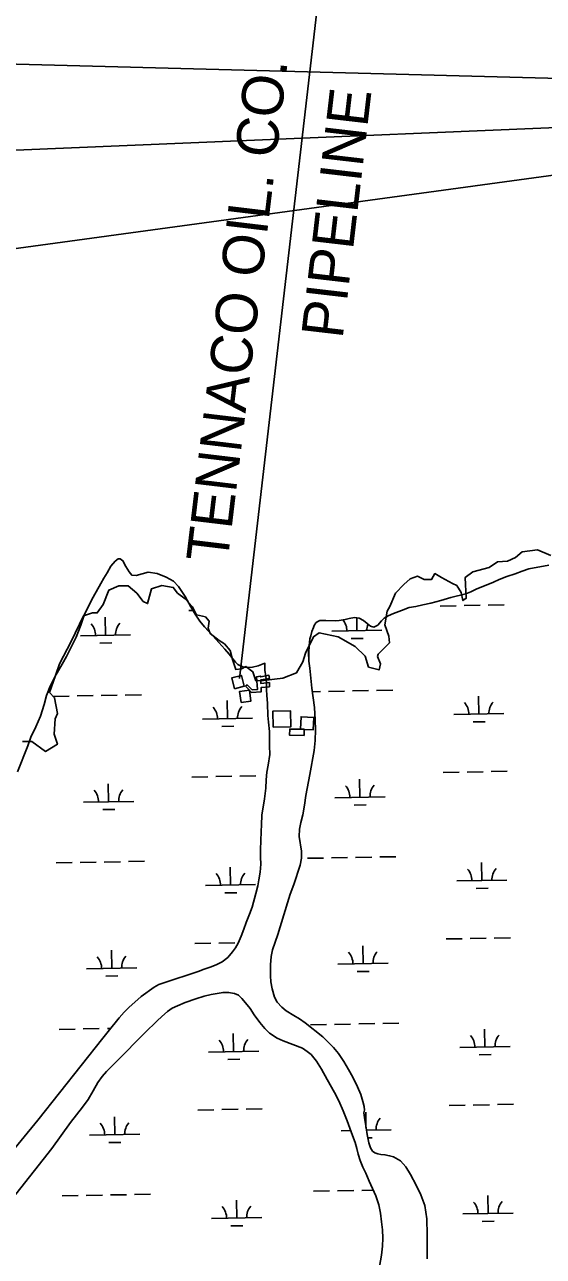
# Model space of a CAD drawing. Extents: x 3957609 to 3995875, y 234277 to 260273.
# Drawn here: x 3969134 to 3970170, y 243942 to 246402 of the extents above; entities that cross this region are included whole.
import ezdxf

# ---------------------------------------------------------------- set-up
doc = ezdxf.new("R2010")
doc.units = 0
for name, color, linetype in [('V-BLDG-OTLN', 7, 'Continuous'), ('V-CHAN-DOCK', 7, 'Continuous'), ('V-RIVR-EDGE', 7, 'Continuous'), ('V-TOPO-MINR', 7, 'Continuous'), ('V-TOPO-SHOR', 7, 'Continuous'), ('V-UTIL-IDEN', 7, 'Continuous'), ('V-UTIL-LINE', 7, 'Continuous'), ('V-WETL-SWMP', 7, 'Continuous')]:
    doc.layers.add(name, color=color, linetype=linetype)

msp = doc.modelspace()

# ---------------------------------------------------------------- linework, layer by layer
at = {"layer": 'V-BLDG-OTLN'}
for points in [[(3969553.369, 245075.43), (3969547.733, 245097.137), (3969567.135, 245102.175), (3969572.771, 245080.468)], [(3969566.263, 245048.294), (3969563.363, 245070.159), (3969583.239, 245072.792), (3969586.137, 245050.93)], [(3969630.261, 244998.835), (3969629.929, 245030.857), (3969665.173, 245031.222), (3969665.507, 244999.199)], [(3969692.289, 244994.366), (3969692.291, 244994.85), (3969685.18, 244994.893), (3969686.347, 245019.466), (3969711.681, 245018.264), (3969710.506, 244993.502)], [(3969685.18, 244994.893), (3969685.172, 244994.704), (3969692.289, 244994.366), (3969692.215, 244982.361), (3969663.342, 244982.535), (3969663.418, 244995.022)], [(3969692.289, 244994.366), (3969685.172, 244994.704), (3969685.18, 244994.893), (3969692.291, 244994.85)]]:
    msp.add_lwpolyline(points, close=True, dxfattribs=at)
at = {"layer": 'V-CHAN-DOCK'}
msp.add_lwpolyline([(3969575.219, 245080.575), (3969587.021, 245068.369), (3969606.639, 245069.602), (3969606.633, 245078.31), (3969622.841, 245079.7), (3969623.038, 245087.98), (3969606.011, 245085.951), (3969606.051, 245093.467), (3969622.907, 245095.859), (3969622.03, 245102.603), (3969605.519, 245099.056), (3969605.064, 245100.971), (3969597.468, 245099.453), (3969599.5, 245074.218), (3969588.619, 245073.157), (3969578.563, 245083.231), (3969575.219, 245080.575)], dxfattribs=at)
at = {"layer": 'V-RIVR-EDGE'}
for points in [[(3969695.061, 245146.435), (3969711.158, 245179.575), (3969722.52, 245187.15), (3969760.395, 245179.575), (3969794.482, 245159.691), (3969814.366, 245140.754), (3969820.994, 245118.976), (3969841.825, 245113.295), (3969844.666, 245125.604), (3969838.985, 245139.807), (3969839.931, 245144.541), (3969851.294, 245155.904), (3969862.656, 245167.266), (3969861.709, 245180.522), (3969853.187, 245203.247), (3969857.922, 245230.706), (3969863.603, 245240.175), (3969874.965, 245266.687), (3969891.062, 245283.73), (3969904.318, 245295.093), (3969918.521, 245300.774), (3969931.777, 245294.146), (3969946.927, 245294.146), (3969953.555, 245305.508), (3969966.811, 245297.933), (3969988.589, 245285.624), (3969997.111, 245281.837), (3970005.633, 245267.634), (3970009.42, 245251.537), (3970016.048, 245256.271), (3970014.155, 245297.933), (3970029.304, 245309.296), (3970061.498, 245317.817), (3970078.541, 245329.18), (3970098.426, 245330.127), (3970114.522, 245337.702), (3970127.778, 245349.064), (3970158.078, 245352.851), (3970184.59, 245341.489)], [(3969129.783, 244970.318), (3969148.72, 244970.318), (3969176.179, 244950.434), (3969199.851, 244964.637), (3969193.223, 244984.521), (3969195.116, 245015.768), (3969199.851, 245026.183), (3969194.169, 245057.43), (3969183.754, 245067.845), (3969196.063, 245101.932), (3969203.638, 245125.604), (3969227.31, 245170.107), (3969251.928, 245221.237), (3969269.919, 245226.918), (3969279.387, 245226.918), (3969290.75, 245243.962), (3969302.112, 245272.368), (3969321.996, 245280.89), (3969340.933, 245280.89), (3969357.977, 245266.687), (3969371.233, 245249.643), (3969379.755, 245245.856), (3969387.33, 245275.209), (3969408.161, 245281.837), (3969430.886, 245278.049), (3969439.407, 245266.687), (3969454.557, 245255.324), (3969469.707, 245239.228), (3969477.282, 245223.131), (3969495.272, 245219.343), (3969502.847, 245210.822), (3969500.954, 245196.619), (3969504.741, 245186.203), (3969522.732, 245172), (3969533.147, 245165.372), (3969544.509, 245152.116), (3969549.244, 245134.126), (3969555.872, 245114.241), (3969567.234, 245115.188), (3969575.756, 245119.923), (3969589.959, 245109.507), (3969595.64, 245091.517)], [(3969595.69, 245091.497), (3969611.081, 245091.94), (3969649.615, 245096.812), (3969677.076, 245107.442), (3969689.921, 245129.146), (3969695.015, 245146.641)]]:
    msp.add_lwpolyline(points, dxfattribs=at)
at = {"layer": 'V-TOPO-MINR'}
for points in [[(3968018.214, 246314.387), (3968169.95, 246323.752), (3968183.086, 246324.466), (3968196.227, 246325.051), (3968209.375, 246325.442), (3968222.528, 246325.705), (3968477.968, 246328.931), (3968618.838, 246329.888), (3968759.702, 246329.746), (3968900.553, 246327.959), (3969041.398, 246325.074), (3970886.166, 246276.501), (3970886.6, 246276.508), (3970887.46, 246276.621), (3970887.884, 246276.714), (3971224.276, 246358.726)], [(3967984.26, 246085.689), (3968092.213, 246090.995), (3968141.873, 246093.558), (3968191.524, 246096.284), (3968241.162, 246099.254), (3968290.79, 246102.387), (3968851.891, 246139.195), (3968877.6, 246141.493), (3970879.56, 246225.354), (3970881.146, 246225.397), (3970884.286, 246225.855), (3970885.836, 246226.204), (3971195.807, 246303.452)], [(3967993.694, 245839.928), (3968037.136, 245840.981), (3968087.474, 245842.556), (3968178.984, 245845.901), (3968183.56, 245846.084), (3968188.135, 245846.289), (3968192.709, 245846.525), (3968197.281, 245846.782), (3968292.438, 245852.461), (3968344.567, 245855.838), (3968396.67, 245859.567), (3968448.732, 245863.824), (3970882.382, 246196.277), (3970883.256, 246197.118), (3970883.849, 246197.376), (3970910.475, 246204.139), (3970924.528, 246207.257), (3970938.667, 246209.799), (3970952.935, 246211.476), (3970967.288, 246212.578), (3971208.52, 246223.719)]]:
    msp.add_lwpolyline(points, dxfattribs=at)
at = {"layer": 'V-TOPO-SHOR'}
msp.add_line((3969613.588, 245117.869), (3969613.92, 245126.46), dxfattribs=at)
for points in [[(3969703.704, 245174.973), (3969702.312, 245161.073), (3969701.353, 245148.409), (3969701.406, 245130.781), (3969703.366, 245116.683), (3969707.733, 245076.571), (3969712.894, 245037.995), (3969714.088, 245013.699), (3969714.722, 244993.59), (3969714.26, 244972.414), (3969712.57, 244951.872), (3969703.53, 244904.379), (3969695.807, 244862.278), (3969692.899, 244843.148), (3969689.682, 244823.866), (3969685.749, 244808.617), (3969682.925, 244795.204), (3969682.247, 244780.371), (3969687.238, 244751.383), (3969687.185, 244737.16), (3969684.658, 244722.816), (3969672.042, 244684.651), (3969664.491, 244665.124), (3969658.833, 244648.043), (3969639.975, 244584.611), (3969629.165, 244553.69), (3969626.499, 244540.429), (3969625.331, 244523.902), (3969625.172, 244502.256), (3969626.077, 244490.028), (3969628.807, 244475.763), (3969633.05, 244459.156), (3969638.324, 244449.647), (3969647.919, 244439.612), (3969656.311, 244431.914), (3969671.643, 244422.878), (3969683.292, 244415.751), (3969694.163, 244408.325), (3969729.931, 244379.819), (3969741.824, 244368.358), (3969751.267, 244358.481), (3969760.839, 244346.899), (3969771.434, 244330.974), (3969780.936, 244314.6), (3969789.223, 244299.635), (3969798.989, 244280.011), (3969805.269, 244265.229), (3969809.703, 244251.096), (3969812.185, 244241.007), (3969812.537, 244233.272), (3969811.691, 244228.336), (3969812.795, 244219.198), (3969814.364, 244210.052), (3969815.894, 244198.278), (3969818.171, 244184.794), (3969821.182, 244168.512), (3969824.589, 244158.26), (3969828.669, 244151.704), (3969833.414, 244148.389), (3969839.257, 244146.14), (3969845.739, 244145.272), (3969853.614, 244144.54), (3969863.016, 244142.392), (3969870.715, 244140.117), (3969884.52, 244132.494), (3969895.17, 244120.589), (3969904.529, 244104.989), (3969915.973, 244083.795), (3969925.585, 244064.173), (3969933.627, 244043.025), (3969937.569, 244016.372), (3969938.04, 243984.823), (3969937.639, 243957.306), (3969937.957, 243936.582)], [(3969066.328, 244098.768), (3969160.923, 244213.361), (3969290.098, 244377.552), (3969300.957, 244390.538), (3969323.006, 244418.204), (3969332.91, 244429.348), (3969342.165, 244438.492), (3969367.228, 244460.856), (3969392.705, 244479.661), (3969402.208, 244484.469), (3969411.844, 244487.886), (3969480.521, 244510.856), (3969492.807, 244515.626), (3969504.616, 244519.63), (3969516.742, 244524.09), (3969528.735, 244530.103), (3969539.993, 244538.752), (3969549.432, 244549.903), (3969555.423, 244557.702), (3969560.821, 244567.52), (3969566.9, 244581.346), (3969572.053, 244595.498), (3969576.417, 244608.576), (3969583.302, 244624.868), (3969588.457, 244639.173), (3969596.127, 244666.739), (3969599.75, 244681.995), (3969602.087, 244693.867), (3969604.47, 244708.986), (3969605.632, 244725.048), (3969605.064, 244739.284), (3969605.134, 244754.59), (3969605.539, 244771.902), (3969606.271, 244790.291), (3969607.393, 244803.728), (3969607.829, 244823.205), (3969612.935, 244855.293), (3969616.033, 244877.049), (3969616.279, 244893.899), (3969617.582, 244909.034), (3969620.566, 244922.905), (3969624.127, 244944.501), (3969623.445, 244961.52), (3969623.476, 244974.2), (3969623.24, 244989.975), (3969620.887, 245008.872), (3969619.529, 245021.881), (3969618.954, 245046.166), (3969617.651, 245062.884), (3969617.18, 245073.095), (3969617.221, 245086.549), (3969615.581, 245101.262), (3969613.574, 245112.114), (3969613.588, 245117.869)], [(3969843.058, 243921.263), (3969847.097, 243943.781), (3969848.752, 243962.002), (3969849.45, 243978.073), (3969849.071, 243994.625), (3969846.829, 244010.583), (3969844.611, 244028.087), (3969841.287, 244044.217), (3969835.21, 244062.242), (3969822.337, 244091.497), (3969815.464, 244107.988), (3969809.762, 244119.977), (3969804.386, 244133.043), (3969799.932, 244145.788), (3969797.312, 244157.113), (3969793.929, 244168.914), (3969789.028, 244182.901), (3969783.521, 244197.516), (3969778.477, 244212.278), (3969770.416, 244232.187), (3969761.274, 244252.112), (3969753.016, 244269.085), (3969738.084, 244294.97), (3969726.787, 244315.7), (3969717.125, 244331.766), (3969706.338, 244344.911), (3969698.541, 244351.055), (3969689.045, 244357.223), (3969650.143, 244372.323), (3969638.31, 244377.287), (3969623.455, 244387.245), (3969613.85, 244396.661), (3969603.977, 244408.866), (3969592.758, 244424.182), (3969584.433, 244436.518), (3969575.481, 244448.244), (3969567.877, 244457.014), (3969561.161, 244463.144), (3969553.021, 244466.818), (3969541.607, 244468.837), (3969530.628, 244468.69), (3969506.443, 244464.401), (3969492.793, 244461.352), (3969476.018, 244456.185), (3969454.876, 244448.451), (3969439.17, 244442.338), (3969428.586, 244437.546), (3969419.208, 244430.724), (3969408.393, 244420.521), (3969398.837, 244412.001), (3969374.523, 244388.232), (3969318.033, 244331.377), (3969297.483, 244311.11), (3969288.833, 244301.03), (3969280.456, 244288.627), (3969271.097, 244272.219), (3969260.8, 244255.204), (3969250.056, 244239.434), (3969225.957, 244209.169), (3969188.554, 244156.986), (3969109.631, 244056.698)]]:
    msp.add_lwpolyline(points, dxfattribs=at)
at = {"layer": 'V-UTIL-LINE'}
msp.add_line((3969563.256, 245095.865), (3969783.41, 246998.629), dxfattribs=at)
at = {"layer": 'V-WETL-SWMP'}
for p, q in [((3969462.13, 245231.736), (3969470.115, 245231.882)), ((3969963.955, 245240.861), (3969995.949, 245241.443)), ((3970011.947, 245241.734), (3970043.941, 245242.316)), ((3970059.939, 245242.607), (3970091.934, 245243.188)), ((3969295.937, 245182.277), (3969295.283, 245218.271)), ((3969797.762, 245191.402), (3969797.293, 245217.222)), ((3969245.946, 245181.368), (3969345.929, 245183.186)), ((3969747.771, 245190.493), (3969847.754, 245192.311)), ((3969284.22, 245166.63), (3969308.216, 245167.067)), ((3969786.045, 245175.755), (3969810.041, 245176.191)), ((3969191.294, 245060.283), (3969223.289, 245060.865)), ((3969239.286, 245061.156), (3969271.281, 245061.738)), ((3969287.278, 245062.029), (3969319.273, 245062.61)), ((3969335.27, 245062.901), (3969367.265, 245063.483)), ((3969708.653, 245069.691), (3969725.114, 245069.99)), ((3969741.111, 245070.281), (3969773.106, 245070.862)), ((3969789.103, 245071.153), (3969821.098, 245071.735)), ((3969837.095, 245072.026), (3969869.09, 245072.608)), ((3970041.3, 245024.989), (3970040.646, 245060.983)), ((3969539.475, 245015.864), (3969538.821, 245051.858)), ((3969489.483, 245014.955), (3969589.467, 245016.773)), ((3969991.308, 245024.08), (3970091.292, 245025.898)), ((3970029.583, 245009.342), (3970053.579, 245009.778)), ((3969527.758, 245000.217), (3969551.754, 245000.654)), ((3969970.003, 244908.241), (3970001.997, 244908.823)), ((3970017.995, 244909.114), (3970049.99, 244909.696)), ((3970065.987, 244909.986), (3970097.982, 244910.568)), ((3969301.985, 244849.657), (3969301.331, 244885.651)), ((3969468.178, 244899.116), (3969500.172, 244899.698)), ((3969516.17, 244899.989), (3969548.164, 244900.571)), ((3969564.162, 244900.862), (3969596.157, 244901.444)), ((3969803.81, 244858.782), (3969803.156, 244894.776)), ((3969753.819, 244857.873), (3969853.802, 244859.691)), ((3969251.994, 244848.748), (3969351.977, 244850.566)), ((3969290.268, 244834.01), (3969314.264, 244834.447)), ((3969792.093, 244843.135), (3969816.089, 244843.571)), ((3969699.167, 244736.788), (3969731.162, 244737.37)), ((3969747.159, 244737.661), (3969779.154, 244738.242)), ((3969795.151, 244738.533), (3969827.146, 244739.115)), ((3969843.143, 244739.406), (3969875.138, 244739.988)), ((3969197.342, 244727.663), (3969229.337, 244728.245)), ((3969245.334, 244728.536), (3969277.329, 244729.118)), ((3969293.326, 244729.409), (3969325.321, 244729.99)), ((3969341.318, 244730.281), (3969373.313, 244730.863)), ((3969545.523, 244683.244), (3969544.869, 244719.238)), ((3970047.348, 244692.369), (3970046.694, 244728.363)), ((3969997.356, 244691.46), (3970097.34, 244693.278)), ((3969495.531, 244682.335), (3969595.515, 244684.153)), ((3969533.806, 244667.597), (3969557.802, 244668.034)), ((3970035.631, 244676.722), (3970059.627, 244677.158)), ((3969474.226, 244566.496), (3969506.22, 244567.078)), ((3969522.218, 244567.369), (3969554.213, 244567.951)), ((3969976.051, 244575.621), (3970008.045, 244576.203)), ((3970024.043, 244576.494), (3970056.038, 244577.076)), ((3970072.035, 244577.366), (3970104.03, 244577.948)), ((3969308.033, 244517.037), (3969307.379, 244553.031)), ((3969809.858, 244526.162), (3969809.204, 244562.156)), ((3969258.042, 244516.128), (3969358.025, 244517.946)), ((3969759.867, 244525.253), (3969859.85, 244527.071)), ((3969296.316, 244501.39), (3969320.312, 244501.827)), ((3969798.141, 244510.515), (3969822.137, 244510.951)), ((3969203.39, 244395.043), (3969235.385, 244395.625)), ((3969251.382, 244395.916), (3969283.377, 244396.498)), ((3969299.374, 244396.789), (3969306.035, 244396.91)), ((3969705.215, 244404.168), (3969737.21, 244404.75)), ((3969753.207, 244405.041), (3969785.202, 244405.622)), ((3969801.199, 244405.913), (3969833.194, 244406.495)), ((3969849.191, 244406.786), (3969881.186, 244407.368)), ((3970053.396, 244359.749), (3970052.742, 244395.743)), ((3969551.571, 244350.624), (3969550.917, 244386.618)), ((3969501.579, 244349.715), (3969601.563, 244351.533)), ((3970003.404, 244358.84), (3970103.388, 244360.658)), ((3970041.679, 244344.102), (3970065.675, 244344.538)), ((3969539.854, 244334.977), (3969563.85, 244335.414)), ((3969982.099, 244243.001), (3970014.094, 244243.583)), ((3970030.091, 244243.874), (3970062.086, 244244.456)), ((3970078.083, 244244.746), (3970110.078, 244245.328)), ((3969314.082, 244184.417), (3969313.427, 244220.411)), ((3969480.274, 244233.876), (3969512.269, 244234.458)), ((3969528.266, 244234.749), (3969560.261, 244235.331)), ((3969576.258, 244235.622), (3969608.253, 244236.203)), ((3969815.809, 244198.927), (3969815.252, 244229.536)), ((3969816.691, 244193.556), (3969865.898, 244194.451)), ((3969264.09, 244183.508), (3969364.073, 244185.326)), ((3969302.364, 244168.77), (3969326.36, 244169.207)), ((3969765.915, 244192.633), (3969785.228, 244192.984)), ((3969819.396, 244178.171), (3969828.185, 244178.331)), ((3969711.263, 244071.548), (3969743.258, 244072.13)), ((3969759.255, 244072.421), (3969791.25, 244073.002)), ((3969807.247, 244073.293), (3969830.164, 244073.71)), ((3969209.438, 244062.423), (3969241.433, 244063.005)), ((3969257.43, 244063.296), (3969289.425, 244063.878)), ((3969305.422, 244064.169), (3969337.417, 244064.75)), ((3969353.414, 244065.041), (3969385.409, 244065.623)), ((3969557.619, 244018.004), (3969556.965, 244053.998)), ((3970059.444, 244027.129), (3970058.79, 244063.123)), ((3970009.452, 244026.22), (3970109.436, 244028.038)), ((3969507.627, 244017.095), (3969607.611, 244018.913)), ((3969545.902, 244002.357), (3969569.898, 244002.794)), ((3970047.727, 244011.482), (3970071.723, 244011.918))]:
    msp.add_line(p, q, dxfattribs=at)
for points in [[(3969119.74, 244909.386), (3969140.36, 244961.386), (3969146.353, 244978.681), (3969156.738, 244999.17), (3969165.747, 245021.077), (3969172.912, 245044.251), (3969177.668, 245061.874), (3969185.24, 245081.008), (3969194.82, 245099.492), (3969209.309, 245124.733), (3969217.603, 245140.132), (3969237.253, 245178.799), (3969246.291, 245202.723), (3969253.094, 245222.333), (3969261.584, 245240.523), (3969270.851, 245258.856), (3969286.611, 245286.096), (3969292.347, 245296.411), (3969298.867, 245307.179), (3969306.508, 245320.415), (3969315.033, 245330.378), (3969321.003, 245335.413), (3969324.88, 245335.202), (3969330.41, 245331.242), (3969336.607, 245319.823), (3969342.813, 245309.024), (3969347.996, 245302.586), (3969356.984, 245301.68), (3969381.137, 245308.468), (3969398.793, 245306.038), (3969416.533, 245298.642), (3969431.619, 245290.198), (3969441.56, 245280.121), (3969454.764, 245259.599), (3969465.953, 245239.262), (3969474.425, 245224.24), (3969484.16, 245210.597), (3969493.149, 245199.138), (3969510.268, 245181.042), (3969533.935, 245154.316), (3969542.488, 245144.88), (3969549.798, 245135.307), (3969554.981, 245128.869), (3969560.027, 245123.674), (3969569.582, 245119.035), (3969579.341, 245117.807), (3969589.445, 245118.902)], [(3969671.643, 244422.878), (3969656.312, 244431.914), (3969647.919, 244439.613), (3969638.324, 244449.648), (3969633.05, 244459.157), (3969628.807, 244475.763), (3969626.076, 244490.028), (3969625.172, 244502.257), (3969625.331, 244523.902), (3969626.499, 244540.43), (3969629.166, 244553.689), (3969639.975, 244584.611), (3969658.832, 244648.043), (3969664.492, 244665.124), (3969672.043, 244684.652), (3969684.658, 244722.815), (3969687.186, 244737.159), (3969687.238, 244751.383), (3969682.247, 244780.371), (3969682.926, 244795.205), (3969685.75, 244808.616), (3969689.682, 244823.867), (3969692.9, 244843.148), (3969695.807, 244862.279), (3969703.531, 244904.38), (3969712.57, 244951.873), (3969714.26, 244972.413), (3969714.723, 244993.59), (3969714.087, 245013.7), (3969712.893, 245037.994), (3969707.733, 245076.57), (3969703.367, 245116.682), (3969701.407, 245130.781), (3969701.354, 245148.409), (3969702.311, 245161.074), (3969703.704, 245174.974), (3969705.969, 245181.303), (3969707.797, 245189.657), (3969710.714, 245198.15), (3969712.634, 245202.158), (3969715.967, 245207.231), (3969718.634, 245209.209), (3969723.95, 245211.926), (3969728.765, 245212.166), (3969735.439, 245212.224), (3969754.361, 245211.484), (3969762.439, 245211.987), (3969773.952, 245213.993), (3969782.357, 245215.733), (3969792.627, 245217.601), (3969801.928, 245216.845), (3969810.547, 245211.909), (3969818.215, 245205.59), (3969824.506, 245200.688), (3969831.77, 245198.565), (3969839.429, 245202.334), (3969846.85, 245211.072), (3969852.202, 245216.271), (3969860.189, 245221.276), (3969870.497, 245225.782), (3969886.418, 245232.069), (3969901.707, 245237.589), (3969915.091, 245240.188), (3969929.571, 245243.392), (3969945.289, 245246.422), (3969965.541, 245251.715), (3969985.033, 245258.105), (3970015.089, 245265.273), (3970025.39, 245269.314), (3970035.867, 245274.749), (3970070.677, 245288.676), (3970081.929, 245294.099), (3970096.913, 245299.934), (3970113.753, 245305.432), (3970127.329, 245310.511), (3970140.893, 245314.815), (3970181.039, 245322.146)], [(3969589.445, 245118.902), (3969600.501, 245121.535), (3969613.919, 245126.461), (3969613.589, 245117.868), (3969613.573, 245112.114), (3969615.58, 245101.261), (3969617.222, 245086.548), (3969617.181, 245073.096), (3969617.651, 245062.884), (3969618.954, 245046.166), (3969619.53, 245021.881), (3969620.887, 245008.873), (3969623.241, 244989.975), (3969623.476, 244974.2), (3969623.446, 244961.521), (3969624.127, 244944.502), (3969620.566, 244922.906), (3969617.581, 244909.034), (3969616.279, 244893.899), (3969616.034, 244877.049), (3969612.935, 244855.292), (3969607.83, 244823.204), (3969607.393, 244803.728), (3969606.27, 244790.292), (3969605.539, 244771.902), (3969605.133, 244754.59), (3969605.065, 244739.283), (3969605.632, 244725.049), (3969604.471, 244708.985), (3969602.086, 244693.867), (3969599.749, 244681.994), (3969596.126, 244666.739), (3969588.458, 244639.173), (3969583.302, 244624.868), (3969576.417, 244608.577), (3969572.052, 244595.498), (3969566.899, 244581.347), (3969560.822, 244567.519), (3969555.422, 244557.702), (3969549.433, 244549.903), (3969539.994, 244538.752), (3969528.735, 244530.102), (3969516.742, 244524.091), (3969504.616, 244519.629), (3969492.807, 244515.625), (3969480.522, 244510.856), (3969411.844, 244487.886), (3969402.208, 244484.47), (3969392.706, 244479.66), (3969367.229, 244460.857), (3969342.164, 244438.491), (3969332.909, 244429.348), (3969323.006, 244418.204), (3969300.956, 244390.537), (3969290.099, 244377.552), (3969160.922, 244213.361), (3969066.328, 244098.767)], [(3969109.631, 244056.698), (3969188.554, 244156.986), (3969225.958, 244209.169), (3969250.055, 244239.435), (3969260.799, 244255.205), (3969271.096, 244272.219), (3969280.457, 244288.628), (3969288.833, 244301.031), (3969297.483, 244311.111), (3969318.034, 244331.377), (3969374.524, 244388.232), (3969398.836, 244412), (3969408.392, 244420.52), (3969419.209, 244430.723), (3969428.586, 244437.545), (3969439.17, 244442.339), (3969454.876, 244448.451), (3969476.017, 244456.184), (3969492.792, 244461.352), (3969506.443, 244464.401), (3969530.627, 244468.689), (3969541.607, 244468.838), (3969553.02, 244466.817), (3969561.162, 244463.143), (3969567.876, 244457.015), (3969575.48, 244448.245), (3969584.433, 244436.518), (3969592.758, 244424.182), (3969603.977, 244408.866), (3969613.851, 244396.662), (3969623.455, 244387.245), (3969638.309, 244377.288), (3969650.143, 244372.323), (3969689.044, 244357.223), (3969698.541, 244351.055), (3969706.338, 244344.911), (3969717.125, 244331.766), (3969726.788, 244315.699), (3969738.084, 244294.97), (3969753.016, 244269.086), (3969761.273, 244252.112), (3969770.416, 244232.187), (3969778.477, 244212.278), (3969783.52, 244197.515), (3969789.028, 244182.901), (3969793.928, 244168.913), (3969797.313, 244157.113), (3969799.932, 244145.787), (3969804.385, 244133.043), (3969809.762, 244119.977), (3969815.464, 244107.988), (3969822.337, 244091.498), (3969835.21, 244062.241), (3969841.287, 244044.217), (3969844.61, 244028.087), (3969846.829, 244010.582), (3969849.071, 243994.624), (3969849.45, 243978.073), (3969848.752, 243962.002), (3969847.096, 243943.781), (3969843.058, 243921.264)], [(3969937.957, 243936.582), (3969937.64, 243957.306), (3969938.04, 243984.823), (3969937.57, 244016.373), (3969933.628, 244043.026), (3969925.585, 244064.172), (3969915.974, 244083.794), (3969904.53, 244104.989), (3969895.17, 244120.588), (3969884.52, 244132.494), (3969870.714, 244140.116), (3969863.016, 244142.393), (3969853.614, 244144.54), (3969845.739, 244145.272), (3969839.257, 244146.14), (3969833.414, 244148.389), (3969828.669, 244151.705), (3969824.589, 244158.259), (3969821.182, 244168.513), (3969818.171, 244184.793), (3969815.893, 244198.278), (3969814.363, 244210.052), (3969812.795, 244219.198), (3969811.691, 244228.336), (3969812.536, 244233.272), (3969812.184, 244241.008), (3969809.702, 244251.095), (3969805.269, 244265.23), (3969798.989, 244280.011), (3969789.223, 244299.635), (3969780.936, 244314.6), (3969771.433, 244330.973), (3969760.84, 244346.899), (3969751.267, 244358.48), (3969741.824, 244368.359), (3969729.93, 244379.819), (3969694.162, 244408.325), (3969683.291, 244415.751), (3969671.643, 244422.878)]]:
    msp.add_lwpolyline(points, dxfattribs=at)
for centre, start, end in [((3969240.695, 245181.747), 0.269879, 41.813537), ((3969351.163, 245183.756), 140.269876, 181.813534), ((3969742.52, 245190.872), 0.269879, 39.432994), ((3969852.988, 245192.881), 160.854926, 181.813534), ((3969484.233, 245015.334), 0.269879, 41.813537), ((3969594.7, 245017.343), 140.269876, 181.813534), ((3969986.058, 245024.459), 0.269879, 41.813537), ((3970096.525, 245026.468), 140.269876, 181.813534), ((3969859.036, 244860.261), 140.269876, 181.813534), ((3969246.743, 244849.127), 0.269879, 41.813537), ((3969357.211, 244851.136), 140.269876, 181.813534), ((3969748.568, 244858.252), 0.269879, 41.813537), ((3969992.106, 244691.839), 0.269879, 41.813537), ((3970102.573, 244693.848), 140.269876, 181.813534), ((3969490.281, 244682.714), 0.269879, 41.813537), ((3969600.748, 244684.723), 140.269876, 181.813534), ((3969252.791, 244516.507), 0.269879, 41.813537), ((3969363.259, 244518.516), 140.269876, 181.813534), ((3969754.616, 244525.632), 0.269879, 41.813537), ((3969865.084, 244527.641), 140.269876, 181.813534), ((3969496.329, 244350.094), 0.269879, 41.813537), ((3969606.796, 244352.103), 140.269876, 181.813534), ((3969998.154, 244359.219), 0.269879, 41.813537), ((3970108.621, 244361.228), 140.269876, 181.813534), ((3969258.839, 244183.887), 0.269879, 41.813537), ((3969369.307, 244185.896), 140.269876, 181.813534), ((3969871.132, 244195.021), 140.269876, 181.813534), ((3970004.202, 244026.599), 0.269879, 41.813537), ((3970114.669, 244028.608), 140.269876, 181.813534), ((3969502.377, 244017.474), 0.269879, 41.813537), ((3969612.844, 244019.483), 140.269876, 181.813534)]:
    msp.add_arc(centre, 35.246, start, end, dxfattribs=at)

# ---------------------------------------------------------------- texts
at = {"layer": 'V-UTIL-IDEN'}
for s, height, rotation, p in [('TENNACO OIL. CO.', 82.99983, 83.150868, (3969539.132, 245325.173)), ('PIPELINE', 82.9998, 83.337358, (3969768.978, 245773.336))]:
    msp.add_text(s, height=height, rotation=rotation, dxfattribs=at).set_placement(p)

doc.saveas('drawing.dxf')
